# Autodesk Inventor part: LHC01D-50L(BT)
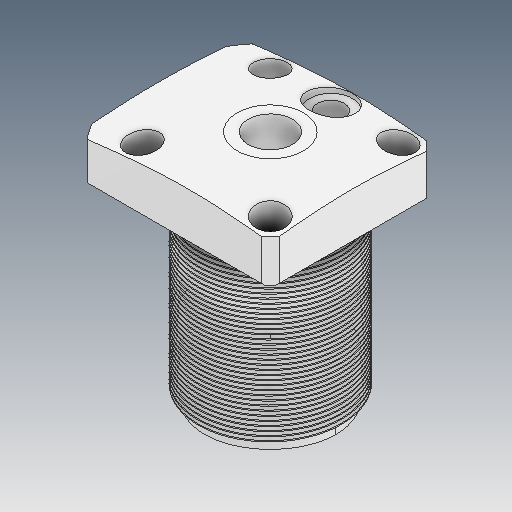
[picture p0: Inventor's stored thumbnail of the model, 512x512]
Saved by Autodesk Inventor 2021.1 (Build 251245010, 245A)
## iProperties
Created: 2021-06
Part Number: LHC01D-50L(BT)
Material: Ogólny
Document SubType Name: Modeling
Designer: user
Density: 1 g/cm^3
Appearance: Domyślna
Author: user
Revision Number: ÈÎºÎ
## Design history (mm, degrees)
feature "NONE"
node "Bryła1"
